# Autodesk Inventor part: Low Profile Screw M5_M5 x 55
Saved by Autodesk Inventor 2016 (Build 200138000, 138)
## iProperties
Created: 2016-01
Part Number: Low Profile Screw M5_M5 x 55
Material: Generic
Document SubType Name: Modeling
Designer: John
Density: 1 g/cm^3
Appearance: Default
Author: John
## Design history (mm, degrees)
feature "CUT-EXTRUDE2"
body "Solid1"
